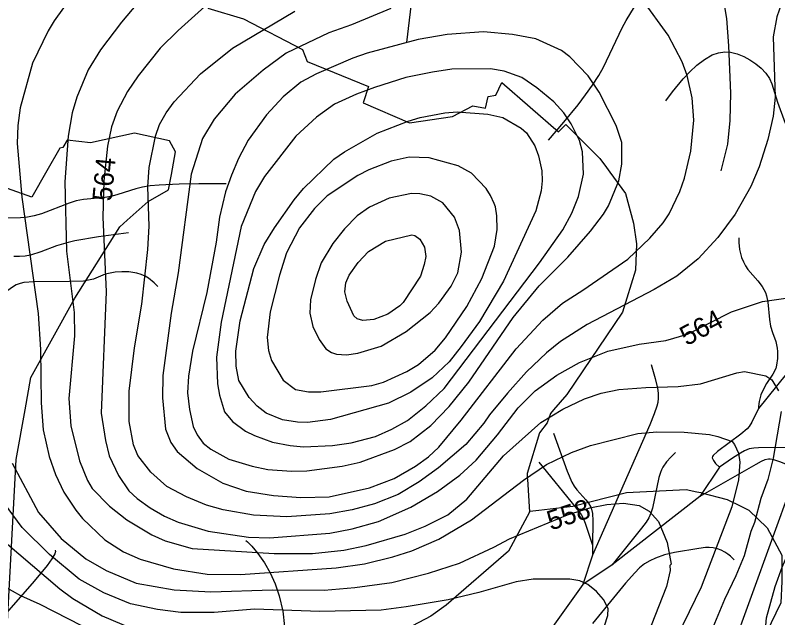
# Model space of a CAD drawing. Extents: x -709584 to -702006, y -1161789 to -1157496.
# Drawn here: x -707587.5 to -707197.2, y -1158314.1 to -1158005.6 of the extents above; entities that cross this region are included whole.
import ezdxf

# ---------------------------------------------------------------- set-up
doc = ezdxf.new("R2010")
doc.units = 0
for name, color, linetype in [('120_vrstevnice hlavní', 7, 'Continuous'), ('121_vrstevnice hlavní_popis', 7, 'Continuous'), ('122_vrstevnice základní', 7, 'Continuous'), ('124_vrstevnice doplňková', 7, 'Continuous'), ('408_BPEJ_linie', 7, 'Continuous'), ('411_akumulovaný odtok', 7, 'Continuous')]:
    doc.layers.add(name, color=color, linetype=linetype)

msp = doc.modelspace()

# ---------------------------------------------------------------- linework, layer by layer
at = {"layer": '120_vrstevnice hlavní'}
for points in [[(-707419.96, -1157880.61), (-707429.87, -1157888.25), (-707442.73, -1157895.53), (-707468.44, -1157907.82), (-707477.01, -1157912.68), (-707485.59, -1157918.53), (-707498.16, -1157928.68), (-707512.02, -1157942.11), (-707544.02, -1157976.82), (-707552.45, -1157987.11), (-707567.59, -1158008.4), (-707570.73, -1158013.54), (-707578.73, -1158030.11), (-707585.02, -1158052.97), (-707586.16, -1158062.11)], [(-707278.58, -1158090.4), (-707277, -1158081.83), (-707277, -1158070.69), (-707279.86, -1158062.11), (-707288.58, -1158044.97), (-707294.29, -1158036.68), (-707303.58, -1158026.97), (-707307.86, -1158023.68), (-707321.01, -1158017.68), (-707333.01, -1158015.4), (-707347.87, -1158014.11), (-707366.44, -1158015.54), (-707381.3, -1158017.97), (-707407.3, -1158024.97), (-707414.73, -1158027.54), (-707433.3, -1158035.68), (-707441.3, -1158039.83), (-707450.3, -1158047.4), (-707458.87, -1158056.68), (-707468.3, -1158069.54), (-707473.16, -1158078.97), (-707476.87, -1158087.54), (-707479.87, -1158096.11), (-707483.01, -1158108.97), (-707484.73, -1158121.83), (-707489.44, -1158147.54), (-707496.73, -1158177.55), (-707498.73, -1158190.41), (-707499.3, -1158198.98), (-707498.3, -1158207.55), (-707496.44, -1158216.12), (-707494.44, -1158220.41), (-707491.3, -1158224.69), (-707487.44, -1158227.83), (-707478.16, -1158232.83), (-707466.16, -1158236.55), (-707458.16, -1158238.12), (-707446.16, -1158238.98), (-707438.16, -1158238.83), (-707420.15, -1158236.55), (-707411.01, -1158234.41), (-707393.3, -1158227.98), (-707385.3, -1158223.83), (-707374.72, -1158215.69), (-707365.29, -1158205.98), (-707355.29, -1158193.4), (-707332.58, -1158160.4), (-707319.29, -1158144.12), (-707304.58, -1158129.4), (-707293.01, -1158116.11), (-707286.43, -1158107.54), (-707283.72, -1158103.26), (-707278.58, -1158090.4)], [(-707586.16, -1158062.11), (-707586.45, -1158071.26), (-707584.16, -1158098.69), (-707575.73, -1158158.4), (-707574.59, -1158176.69), (-707574.3, -1158204.12), (-707573.3, -1158217.83), (-707570.16, -1158231.55), (-707566.88, -1158240.69), (-707562.59, -1158249.84), (-707556.45, -1158258.98), (-707553.02, -1158263.27), (-707541.59, -1158274.12), (-707532.16, -1158280.27), (-707523.59, -1158284.12), (-707506.44, -1158289.12), (-707489.3, -1158291.84), (-707472.16, -1158291.98), (-707423.3, -1158288.55), (-707408.73, -1158286.55), (-707394.15, -1158282.98), (-707384.44, -1158279.84), (-707370.58, -1158273.84), (-707354.01, -1158263.98), (-707327.29, -1158243.69), (-707315.58, -1158235.69), (-707302.72, -1158229.41), (-707293.01, -1158225.98), (-707268.72, -1158219.69), (-707259, -1158218.83), (-707245, -1158219.12), (-707232.15, -1158220.26), (-707227.86, -1158221.26), (-707220.57, -1158223.83), (-707219.29, -1158225.41), (-707217.29, -1158229.83), (-707216.57, -1158234.41), (-707217.29, -1158243.55), (-707220.72, -1158257.27), (-707236.43, -1158298.41), (-707251.86, -1158330.41)]]:
    msp.add_lwpolyline(points, dxfattribs=at)
at = {"layer": '122_vrstevnice základní'}
for points in [[(-707348.14, -1157880.61), (-707354.44, -1157888.1), (-707380.3, -1157915.96), (-707396.87, -1157935.25), (-707404.01, -1157942.39), (-707419.58, -1157955.54), (-707473.58, -1157988.82), (-707490.44, -1158001.11), (-707504.16, -1158013.4), (-707513.3, -1158022.4), (-707524.59, -1158036.68), (-707530.02, -1158044.68), (-707535.3, -1158054.68), (-707538.3, -1158062.68)], [(-707512.16, -1157984.11), (-707533.16, -1158009.11), (-707543.87, -1158023.4), (-707550.16, -1158033.54), (-707556.02, -1158047.54), (-707558.3, -1158055.54), (-707560.45, -1158067.54), (-707562.16, -1158090.97), (-707561.3, -1158126.4), (-707557.3, -1158157.83), (-707557.16, -1158169.83), (-707560.16, -1158201.83), (-707559.02, -1158215.83), (-707554.59, -1158233.83), (-707550.59, -1158243.84), (-707548.16, -1158247.84), (-707539.3, -1158256.98), (-707530.3, -1158263.98)], [(-707209.43, -1158372.27), (-707204.29, -1158330.28), (-707202.86, -1158314.12), (-707198.43, -1158298.12), (-707194.86, -1158288.12), (-707187, -1158270.12), (-707174.14, -1158246.12), (-707166.86, -1158230.41), (-707155.71, -1158199.55), (-707150.57, -1158180.69), (-707144.71, -1158151.55), (-707141.28, -1158127.26), (-707139.43, -1158103.26), (-707139.43, -1158095.26), (-707141, -1158071.26), (-707141.57, -1158047.26), (-707143.28, -1158027.25), (-707147, -1158007.25), (-707150.85, -1157993.25)], [(-707395.3, -1158002.25), (-707415.3, -1158010.54), (-707427.01, -1158014.68), (-707448.73, -1158025.11), (-707460.58, -1158033.82), (-707474.87, -1158046.11), (-707485.73, -1158058.83), (-707491.73, -1158068.68), (-707497.44, -1158086.97), (-707504.16, -1158137.54), (-707507.73, -1158158.12), (-707511.87, -1158190.12), (-707512.16, -1158201.55), (-707510.59, -1158217.55), (-707507.87, -1158224.41), (-707504.59, -1158228.98), (-707494.3, -1158237.69), (-707481.3, -1158245.26), (-707469.3, -1158249.26), (-707455.3, -1158251.55), (-707441.3, -1158252.55), (-707426.73, -1158252.26), (-707406.15, -1158247.55), (-707393.58, -1158242.83), (-707382.58, -1158236.55), (-707375.87, -1158231.69), (-707370.58, -1158226.69), (-707359.15, -1158212.98), (-707331.15, -1158176.4), (-707317.44, -1158161.69), (-707307.29, -1158152.97), (-707296.86, -1158146.4), (-707273.86, -1158130.54), (-707262.58, -1158119.69), (-707255.86, -1158111.83), (-707252.72, -1158107.26), (-707247.29, -1158095.83), (-707244.86, -1158088.97), (-707241.57, -1158075.26), (-707240.15, -1158059.26), (-707241, -1158047.83), (-707243.57, -1158036.4), (-707246.15, -1158029.54), (-707253.29, -1158015.82), (-707266.43, -1157997.54)], [(-707195.29, -1157999.54), (-707197.57, -1158006.4), (-707199.57, -1158016.68), (-707198.43, -1158047.54), (-707199.57, -1158057.26), (-707202.29, -1158069.26), (-707206.71, -1158083.26), (-707211, -1158093.26), (-707219, -1158107.54), (-707227.86, -1158119.4), (-707237.86, -1158130.26), (-707248.86, -1158139.12), (-707260.43, -1158145.97), (-707294.72, -1158163.97), (-707308.29, -1158172.69), (-707315.58, -1158178.4), (-707325.72, -1158188.26), (-707335.58, -1158199.12), (-707344.72, -1158210.26), (-707347.58, -1158214.55), (-707356.87, -1158225.41), (-707370.87, -1158237.26)], [(-707370.87, -1158237.26), (-707380.72, -1158244.55), (-707391.44, -1158250.98), (-707403.58, -1158255.84), (-707415.01, -1158258.84), (-707426.44, -1158260.84), (-707448.44, -1158262.41), (-707465.58, -1158261.55), (-707481.01, -1158258.84), (-707489.59, -1158256.41), (-707499.87, -1158252.26), (-707509.87, -1158246.83), (-707518.02, -1158239.55), (-707524.73, -1158230.98), (-707527.02, -1158225.55), (-707529.16, -1158213.55), (-707529.16, -1158198.12), (-707526.45, -1158175.83), (-707522.73, -1158153.55), (-707519.59, -1158125.54), (-707519.02, -1158113.54), (-707519.59, -1158093.54), (-707519.02, -1158083.54), (-707515.73, -1158067.54), (-707513.59, -1158061.54), (-707510.3, -1158055.54), (-707506.16, -1158049.97), (-707492.73, -1158035.68), (-707476.3, -1158022.4), (-707444.3, -1158003.54)], [(-707337.29, -1158034.25), (-707344.15, -1158033.11), (-707363.97, -1158033.16), (-707373.87, -1158034.82), (-707387.58, -1158037.54), (-707403.58, -1158042.54), (-707412.73, -1158045.97), (-707424.15, -1158051.11), (-707433.3, -1158057.83), (-707443.87, -1158067.54), (-707459.87, -1158088.11), (-707464.44, -1158095.83), (-707471.87, -1158113.83), (-707482.16, -1158162.69), (-707484.44, -1158180.69), (-707484.01, -1158194.41), (-707483.01, -1158200.12), (-707480.3, -1158208.69), (-707476.3, -1158213.69), (-707469.58, -1158218.55), (-707465.01, -1158220.83), (-707455.87, -1158224.12), (-707446.73, -1158225.98), (-707439.87, -1158226.55), (-707425.01, -1158225.98), (-707415.58, -1158224.55), (-707403.15, -1158221.26), (-707394.72, -1158217.55), (-707386.72, -1158213.12), (-707377.3, -1158205.55), (-707368.01, -1158196.69), (-707319.15, -1158132.4), (-707307.15, -1158115.54), (-707302.58, -1158106.97), (-707299.15, -1158098.4), (-707296.58, -1158086.97), (-707297.15, -1158075.54), (-707298.72, -1158069.83), (-707302.86, -1158061.26), (-707306.72, -1158055.54), (-707311.86, -1158049.97), (-707320.44, -1158042.83), (-707328.15, -1158037.54), (-707337.29, -1158034.25)], [(-707367.58, -1158055.54), (-707361.29, -1158055.11), (-707345.58, -1158056.26), (-707337.87, -1158057.97), (-707328.44, -1158063.4), (-707325.86, -1158065.83), (-707321.58, -1158072.4), (-707319.58, -1158077.54), (-707317.86, -1158085.26), (-707317.72, -1158090.4), (-707318.29, -1158095.54), (-707321.01, -1158105.83), (-707337.58, -1158141.83), (-707349.87, -1158162.4), (-707359.15, -1158175.26), (-707365.44, -1158182.98), (-707374.01, -1158191.26), (-707385.01, -1158198.55), (-707396.44, -1158204.26), (-707426.15, -1158212.55), (-707437.87, -1158214.12), (-707443.01, -1158213.98), (-707450.73, -1158212.69), (-707459.01, -1158209.26), (-707463.58, -1158205.69), (-707467.73, -1158201.26), (-707473.01, -1158192.55), (-707474.44, -1158185.26), (-707474.58, -1158177.55), (-707472.44, -1158162.12), (-707465.44, -1158135.26), (-707460.01, -1158122.97), (-707454.87, -1158114.4), (-707444.73, -1158100.11), (-707440.01, -1158094.4), (-707424.44, -1158079.26), (-707419.01, -1158075.54), (-707402.15, -1158065.97), (-707386.44, -1158059.83), (-707380.15, -1158057.97), (-707367.58, -1158055.54)], [(-707538.3, -1158062.68), (-707540.3, -1158072.69), (-707542.16, -1158090.4), (-707542.73, -1158108.97), (-707541.02, -1158147.26), (-707543.45, -1158209.26), (-707541.3, -1158223.26), (-707539.45, -1158231.26), (-707534.73, -1158241.26), (-707529.3, -1158249.12), (-707525.16, -1158252.98), (-707518.44, -1158257.84), (-707511.02, -1158262.12), (-707504.16, -1158265.12), (-707488.73, -1158269.69), (-707468.16, -1158272.84), (-707457.3, -1158273.12), (-707426.44, -1158270.84), (-707415.01, -1158268.55), (-707401.58, -1158264.84), (-707385.01, -1158257.41), (-707371.3, -1158249.41), (-707359.87, -1158241.12), (-707351.58, -1158233.41), (-707340.58, -1158220.41), (-707330.01, -1158206.69), (-707321.29, -1158197.83), (-707310.29, -1158189.83), (-707298.58, -1158183.4), (-707284.15, -1158177.55), (-707268.15, -1158173.98), (-707254.43, -1158172.12), (-707243.29, -1158168.97), (-707220.86, -1158157.4), (-707205, -1158152.12), (-707193, -1158150.54)], [(-707353.87, -1158086.54), (-707360.72, -1158082.69), (-707375.58, -1158078.54), (-707385.87, -1158078.26), (-707395.01, -1158080.4), (-707406.44, -1158084.83), (-707412.15, -1158087.69), (-707427.87, -1158098.11), (-707434.3, -1158104.54), (-707442.01, -1158114.4), (-707448.58, -1158127.26), (-707452.3, -1158138.69), (-707457.01, -1158157.55), (-707458.58, -1158170.69), (-707457.87, -1158177.26), (-707456.3, -1158182.4), (-707450.3, -1158192.41), (-707444.01, -1158197.26), (-707437.3, -1158198.4), (-707431.01, -1158198.4), (-707405.01, -1158195.12), (-707399.01, -1158193.55), (-707387.01, -1158187.98), (-707381.01, -1158184.4), (-707372.58, -1158177.12), (-707367.29, -1158170.83), (-707356.29, -1158154.69), (-707348.72, -1158140.4), (-707342.15, -1158123.83), (-707340.86, -1158115.26), (-707341.01, -1158108.4), (-707341.72, -1158103.69), (-707342.29, -1158101.97), (-707344.15, -1158097.83), (-707346.44, -1158094.4), (-707353.87, -1158086.54)], [(-707360.01, -1158115.83), (-707362.58, -1158108.97), (-707368.58, -1158101.69), (-707374.72, -1158098.26), (-707380.44, -1158096.97), (-707384.72, -1158096.83), (-707396.15, -1158099.26), (-707406.15, -1158103.83), (-707412.44, -1158108.4), (-707418.87, -1158114.97), (-707424.87, -1158122.54), (-707430.87, -1158132.4), (-707433.87, -1158140.97), (-707436.3, -1158151.26), (-707436.73, -1158158.12), (-707435.16, -1158164.98), (-707431.87, -1158171.69), (-707428.44, -1158176.4), (-707425.58, -1158178.26), (-707423.01, -1158179.12), (-707417.87, -1158179.55), (-707412.15, -1158178.69), (-707400.15, -1158174.98), (-707387.3, -1158167.55), (-707375.15, -1158157.83), (-707370.58, -1158152.97), (-707364.29, -1158144.4), (-707360.87, -1158137.54), (-707359.01, -1158126.97), (-707360.01, -1158115.83)], [(-707530.3, -1158263.98), (-707517.59, -1158271.55), (-707510.73, -1158274.69), (-707497.02, -1158278.69), (-707455.01, -1158281.27), (-707435.3, -1158281.27), (-707419.3, -1158279.41), (-707407.87, -1158277.12), (-707387.87, -1158271.27), (-707377.58, -1158267.27), (-707366.01, -1158261.41), (-707356.29, -1158253.41), (-707337.58, -1158231.26), (-707318.44, -1158214.12), (-707307.15, -1158207.26), (-707296.01, -1158201.98), (-707287.58, -1158199.12), (-707278.43, -1158197.26), (-707264.72, -1158196.12), (-707248.15, -1158195.69), (-707236.72, -1158194.26), (-707218.14, -1158188.69), (-707214.14, -1158187.98), (-707203.29, -1158190.26), (-707200.14, -1158192.26), (-707196.71, -1158197.98)], [(-707195.43, -1158208.41), (-707199.43, -1158232.41), (-707202.29, -1158243.26), (-707205.86, -1158252.98), (-707209, -1158265.27), (-707210.86, -1158269.98), (-707214.29, -1158282.41), (-707218.57, -1158292.7), (-707224.43, -1158304.7), (-707232.86, -1158325.27), (-707239.57, -1158338.13), (-707244.43, -1158350.13), (-707249.57, -1158368.13), (-707251.15, -1158378.13), (-707251.57, -1158385.84), (-707251.29, -1158401.56), (-707247.29, -1158421.42), (-707246, -1158425.84), (-707240, -1158443.27), (-707237.15, -1158448.84), (-707229, -1158460.7), (-707223.57, -1158466.99), (-707219.14, -1158470.42), (-707187.57, -1158488.99)], [(-707589.02, -1158234.98), (-707575.59, -1158260.12), (-707564.02, -1158273.55), (-707551.3, -1158283.98), (-707541.02, -1158289.98), (-707525.59, -1158296.41), (-707506.16, -1158299.84), (-707487.3, -1158300.84), (-707455.87, -1158299.84), (-707429.3, -1158299.98), (-707413.58, -1158298.55), (-707394.72, -1158295.98), (-707375.87, -1158291.27), (-707360.15, -1158286.12), (-707342.44, -1158277.98), (-707334.44, -1158273.69), (-707304.72, -1158261.41), (-707293.29, -1158257.84), (-707284.72, -1158256.12), (-707276.15, -1158255.41), (-707268.15, -1158256.69), (-707263, -1158259.55), (-707258.15, -1158264.84), (-707253.72, -1158275.55), (-707251.66, -1158286.71), (-707252.43, -1158287.41), (-707252.29, -1158289.84), (-707254.15, -1158298.12), (-707262, -1158318.12)], [(-707190, -1158245.84), (-707221.14, -1158331.84), (-707223.57, -1158341.84), (-707225.29, -1158351.84), (-707225.29, -1158360.98), (-707224.29, -1158366.13), (-707221.29, -1158373.7), (-707220.62, -1158376.03), (-707220.34, -1158379.38), (-707221.74, -1158386.36), (-707225.09, -1158400.88), (-707225.09, -1158407.03), (-707223.86, -1158413.13)], [(-707298.43, -1158295.12), (-707303.58, -1158294.41), (-707322.44, -1158294.27), (-707331.01, -1158295.7), (-707350.15, -1158301.12), (-707365.87, -1158304.84), (-707387.3, -1158308.55), (-707400.15, -1158310.12), (-707431.58, -1158310.84), (-707465.01, -1158309.7), (-707485.59, -1158311.41), (-707502.73, -1158311.41), (-707514.73, -1158309.84), (-707528.45, -1158306.98), (-707542.16, -1158301.41), (-707554.73, -1158294.27), (-707570.02, -1158281.69), (-707584.02, -1158267.84), (-707595.59, -1158252.27)], [(-707592.73, -1158275.41), (-707564.73, -1158299.27), (-707558.02, -1158304.27), (-707543.02, -1158313.12), (-707527.3, -1158319.7)], [(-707539.02, -1158325.55), (-707574.73, -1158307.27), (-707584.73, -1158302.84), (-707606.16, -1158290.84)], [(-707189.86, -1158568.71), (-707226.72, -1158540.42), (-707251.86, -1158519.13), (-707264.58, -1158506.28), (-707278.43, -1158489.71), (-707285.29, -1158480.56), (-707293.72, -1158467.85), (-707299.43, -1158457.56), (-707307.43, -1158438.13), (-707310.15, -1158426.42), (-707311.29, -1158413.56), (-707310.15, -1158396.99), (-707306.72, -1158376.99), (-707300.01, -1158354.98), (-707291.86, -1158332.98), (-707287.43, -1158322.98), (-707284.15, -1158312.98), (-707284, -1158309.41), (-707286.43, -1158304.7), (-707290.01, -1158300.7), (-707294.43, -1158296.98), (-707298.43, -1158295.12)]]:
    msp.add_lwpolyline(points, dxfattribs=at)
at = {"layer": '124_vrstevnice doplňková'}
for points in [[(-707226.09, -1158085.29), (-707222.72, -1158071.54), (-707221.43, -1158059.54), (-707221.14, -1158045.54), (-707222.14, -1158021.25), (-707223.29, -1158007.25), (-707224.29, -1158001.25), (-707227.29, -1157990.54), (-707234, -1157973.54), (-707240.57, -1157963.82), (-707246.64, -1157957.69), (-707251.95, -1157953.29), (-707259.15, -1157949.25), (-707279.58, -1157942.68), (-707285.58, -1157941.53), (-707291.58, -1157941.11), (-707304.15, -1157941.39), (-707317.86, -1157942.82), (-707329.86, -1157944.82), (-707332.86, -1157945.82)], [(-707418.26, -1158142.54), (-707416.58, -1158138.69), (-707412.01, -1158132.26), (-707406.58, -1158126.54), (-707398.01, -1158121.26), (-707384.44, -1158118.11), (-707382.87, -1158118.4), (-707380.3, -1158120.26), (-707377.92, -1158124.35), (-707377.39, -1158129.09), (-707378.15, -1158133.26), (-707380.01, -1158139.12), (-707388.87, -1158152.69), (-707390.58, -1158154.4), (-707396.73, -1158158.69), (-707403.87, -1158161.4), (-707409.58, -1158161.97), (-707412.44, -1158160.97), (-707414.21, -1158159.44), (-707417.54, -1158152.03), (-707418.8, -1158147.17), (-707418.26, -1158142.54)]]:
    msp.add_lwpolyline(points, dxfattribs=at)
at = {"layer": '408_BPEJ_linie'}
for points in [[(-707489, -1158002), (-707470.61, -1158007.48), (-707440.39, -1158023.13), (-707438.05, -1158029.38), (-707406.61, -1158042.06), (-707409.42, -1158050.46), (-707385.74, -1158060.75), (-707363.61, -1158057.39), (-707353.24, -1158052.06), (-707346.8, -1158053.18), (-707345.45, -1158047.2), (-707341.5, -1158046.5), (-707338.41, -1158040.03), (-707309.35, -1158065.35), (-707305.64, -1158061.62), (-707288.3, -1158078.88), (-707284.81, -1158083.59), (-707283.06, -1158085.98), (-707275.1, -1158096.8), (-707271, -1158112), (-707269.53, -1158122.58), (-707269.91, -1158136.07), (-707276.61, -1158157.64), (-707305.14, -1158199.87), (-707311.94, -1158207.71), (-707313.5, -1158209.5), (-707315.23, -1158214.26), (-707319.05, -1158219.41), (-707325.47, -1158240.29), (-707325.36, -1158242.12), (-707325.5, -1158242.5), (-707325.3, -1158243.19), (-707324.29, -1158260.03)], [(-707591.5, -1158316), (-707587, -1158233), (-707582.48, -1158207.71), (-707579.5, -1158191), (-707557, -1158150.5), (-707534, -1158114), (-707530.22, -1158110.61), (-707519.5, -1158101), (-707509, -1158095), (-707507.59, -1158087.11), (-707505.5, -1158075.5), (-707508.5, -1158070), (-707526.5, -1158066), (-707549, -1158071), (-707561, -1158069.5), (-707563.09, -1158073.41), (-707564.7, -1158073.68), (-707571.27, -1158085.27), (-707578.95, -1158098.82), (-707597, -1158092.5)], [(-707324.29, -1158260.03), (-707324, -1158259.5), (-707319.5, -1158259), (-707302, -1158257), (-707274.5, -1158250), (-707244, -1158248.5), (-707238.66, -1158249.57), (-707236.5, -1158250), (-707236.15, -1158250.09), (-707223, -1158253.5), (-707215.63, -1158257.18), (-707212, -1158259), (-707202.5, -1158268), (-707195, -1158282), (-707195, -1158295.5), (-707195.5, -1158306.5)], [(-707324.29, -1158260.03), (-707335, -1158280), (-707366.93, -1158307.56), (-707374.72, -1158313.2), (-707406.54, -1158330.08)], [(-707195.5, -1158306.5), (-707220.5, -1158358), (-707227.18, -1158396.03), (-707231.16, -1158418.72), (-707237, -1158452), (-707238.44, -1158459.36), (-707239.65, -1158465.56), (-707241.5, -1158475), (-707246, -1158489)]]:
    msp.add_lwpolyline(points, dxfattribs=at)
at = {"layer": '411_akumulovaný odtok'}
for p, q in [((-707186.99, -1158182), (-707206.99, -1158207)), ((-707226.99, -1158237), (-707236.99, -1158252)), ((-707236.99, -1158252), (-707281.99, -1158287)), ((-707291.99, -1158277), (-707291.99, -1158282)), ((-707291.99, -1158282), (-707296.99, -1158297)), ((-707281.99, -1158287), (-707296.99, -1158297)), ((-707296.99, -1158297), (-707321.99, -1158332))]:
    msp.add_line(p, q, dxfattribs=at)
for points in [[(-707386.99, -1158019.5), (-707383.75, -1157992.24), (-707382.89, -1157983.22), (-707382.77, -1157978.81), (-707382.88, -1157976.66), (-707383.15, -1157974.57), (-707383.67, -1157972.55), (-707384.45, -1157970.65), (-707386.64, -1157967.05), (-707390.73, -1157961.92), (-707426.99, -1157922)], [(-707314.49, -1158069.5), (-707306.65, -1158060.43), (-707299.3, -1158051.41), (-707295.51, -1158046.45), (-707291.93, -1158041.43), (-707288.79, -1158036.55), (-707286.35, -1158032.19), (-707276.82, -1158012.1), (-707274.72, -1158008.23), (-707266.27, -1157994.19)], [(-707254.49, -1158049.5), (-707251.02, -1158044.87), (-707245.53, -1158038.24), (-707242.15, -1158034.65), (-707238.49, -1158031.22), (-707234.65, -1158028.23), (-707230.72, -1158025.96), (-707227.42, -1158024.78), (-707224.28, -1158024.32), (-707221.41, -1158024.53), (-707217.94, -1158025.41), (-707214.58, -1158026.76), (-707211.36, -1158028.48), (-707208.36, -1158030.49), (-707205.63, -1158032.75), (-707203.27, -1158035.26), (-707201.41, -1158038.02), (-707200.22, -1158040.73), (-707197.26, -1158050.07), (-707193.34, -1158060.8)], [(-707479.49, -1158092), (-707493.55, -1158091.89), (-707503.67, -1158092.04), (-707513.81, -1158092.57), (-707518.37, -1158093.03), (-707522.3, -1158093.67), (-707525.85, -1158094.51), (-707534.92, -1158097.47), (-707537.95, -1158098.27), (-707541.56, -1158098.89), (-707552.61, -1158100.03), (-707556.25, -1158100.71), (-707559.87, -1158101.78), (-707574.15, -1158107.37), (-707577.83, -1158108.4), (-707581.27, -1158108.98), (-707584.79, -1158109.3), (-707599.15, -1158109.62)], [(-707529.49, -1158117), (-707544.85, -1158119.1), (-707556.96, -1158121.19), (-707560.47, -1158121.96), (-707566.41, -1158123.68), (-707574.43, -1158126.79), (-707579.72, -1158128.51), (-707582.4, -1158129.01), (-707585.28, -1158129.18), (-707588.2, -1158129.07)], [(-707216.99, -1158119.5), (-707217.03, -1158122.01), (-707216.68, -1158125.58), (-707215.67, -1158129.71), (-707214.76, -1158131.9), (-707213.63, -1158133.93), (-707212.39, -1158135.76), (-707207.41, -1158141.54), (-707205.17, -1158144.48), (-707203.44, -1158147.63), (-707202.9, -1158149.22), (-707202.24, -1158152.59), (-707201.37, -1158161.36), (-707200.81, -1158164.78), (-707199.84, -1158167.99), (-707198.11, -1158172.58), (-707197.41, -1158176), (-707197.24, -1158177.75), (-707197.23, -1158181.29), (-707197.71, -1158184.74), (-707198.2, -1158186.4), (-707199.67, -1158189.31), (-707202.83, -1158194.18), (-707204.95, -1158198.01), (-707205.77, -1158199.96), (-707206.72, -1158203.39), (-707207.07, -1158205.96), (-707206.99, -1158207)], [(-707514.49, -1158144.5), (-707516.34, -1158142.61), (-707519.26, -1158140.31), (-707521.08, -1158139.23), (-707523.13, -1158138.32), (-707525.27, -1158137.65), (-707529.32, -1158137), (-707532.88, -1158137), (-707536.39, -1158137.23), (-707539.79, -1158137.8), (-707541.42, -1158138.26), (-707547.49, -1158140.72), (-707549.13, -1158141.16), (-707552.56, -1158141.68), (-707559.71, -1158142.01), (-707577.89, -1158142.03), (-707583.19, -1158142.43), (-707585.07, -1158142.9), (-707587.04, -1158143.69), (-707588.93, -1158144.76), (-707592.42, -1158147.44), (-707596.99, -1158152)], [(-707261.99, -1158184.5), (-707259.85, -1158191.6), (-707258.76, -1158196.62), (-707258.45, -1158199.17), (-707258.38, -1158201.59), (-707258.61, -1158203.83), (-707259.08, -1158205.79), (-707260.37, -1158209.62), (-707262.71, -1158215.35), (-707291.99, -1158282)], [(-707206.99, -1158207), (-707210.37, -1158213.89), (-707211.75, -1158216.11), (-707212.84, -1158217.39), (-707216.1, -1158220.13), (-707227.92, -1158228.9), (-707230.22, -1158231), (-707230.56, -1158231.58), (-707230.65, -1158232.26), (-707230.11, -1158233.65), (-707229.02, -1158235.05), (-707226.99, -1158237)], [(-707166.99, -1158217), (-707181.41, -1158224.32), (-707184.8, -1158225.75), (-707187.12, -1158226.44), (-707189.53, -1158226.81), (-707192, -1158226.97), (-707206.98, -1158227.04), (-707209.42, -1158227.24), (-707211.78, -1158227.69), (-707214.09, -1158228.58), (-707216.3, -1158229.77), (-707220.26, -1158232.33), (-707226.99, -1158237)], [(-707311.99, -1158219.5), (-707304.96, -1158239.03), (-707302.63, -1158244.61), (-707301.45, -1158246.68), (-707300.07, -1158248.54), (-707295.41, -1158253.72), (-707293.99, -1158255.5), (-707292.88, -1158257.39), (-707292.49, -1158258.48), (-707292.03, -1158260.78), (-707291.8, -1158264.44), (-707291.99, -1158277)], [(-707249.49, -1158229.5), (-707251.88, -1158231.83), (-707254.02, -1158234.22), (-707255.98, -1158236.98), (-707256.72, -1158238.4), (-707257.26, -1158239.76), (-707257.96, -1158242.31), (-707261.26, -1158258.03), (-707262.05, -1158260.53), (-707263.14, -1158262.9), (-707264.53, -1158265.11), (-707266.89, -1158268.3), (-707281.99, -1158287)], [(-707319.49, -1158234.5), (-707300.81, -1158257.27), (-707297.8, -1158261.31), (-707296.84, -1158263.03), (-707295.7, -1158265.73), (-707291.99, -1158277)], [(-707189.49, -1158237), (-707195.52, -1158234.4), (-707199.09, -1158233.16), (-707200.99, -1158232.85), (-707201.93, -1158232.86), (-707203.81, -1158233.31), (-707205.67, -1158234.11), (-707208.44, -1158235.58), (-707236.99, -1158252)], [(-707469.49, -1158274.5), (-707468.55, -1158275.16), (-707466.34, -1158277.43), (-707463.3, -1158281.11), (-707459.91, -1158286.05), (-707457.08, -1158291.11), (-707454.53, -1158296.8), (-707452.42, -1158302.92), (-707450.6, -1158310.75), (-707449.66, -1158318.57)], [(-707566.99, -1158279.5), (-707566.84, -1158280.1), (-707567.32, -1158281.44), (-707568.8, -1158283.97), (-707571.15, -1158287.27), (-707577.84, -1158295.42), (-707596.9, -1158317.11)], [(-707219.49, -1158284.5), (-707221.34, -1158282.6), (-707222.66, -1158281.52), (-707224.26, -1158280.43), (-707226.07, -1158279.48), (-707228.07, -1158278.77), (-707230.15, -1158278.34), (-707232.2, -1158278.17), (-707234.11, -1158278.2), (-707237.62, -1158278.61), (-707249.99, -1158280.65), (-707255.2, -1158281.85), (-707259.82, -1158283.53), (-707262.63, -1158284.93), (-707265.31, -1158286.55), (-707267.9, -1158288.58), (-707270.4, -1158291.03), (-707275.06, -1158296.37), (-707291.99, -1158317)]]:
    msp.add_lwpolyline(points, dxfattribs=at)

# ---------------------------------------------------------------- texts
at = {"layer": '121_vrstevnice hlavní_popis'}
for s, rotation, p in [('564', 84.7789, (-707538.14, -1158101.09)), ('564', 27.991, (-707243.85, -1158175.12)), ('558', 18.3239, (-707313.31, -1158269.49))]:
    msp.add_text(s, height=10, rotation=rotation, dxfattribs=at).set_placement(p)

doc.saveas('drawing.dxf')
